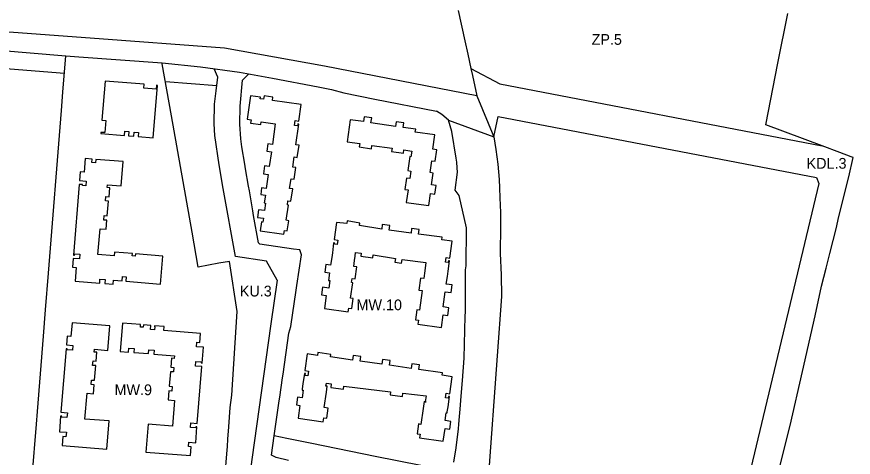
# Model space of a CAD drawing. Extents: x 7427060 to 7429122, y 5545301 to 5546237.
# Drawn here: x 7428222.9 to 7428612.5, y 5545719.4 to 5545924.5 of the extents above; entities that cross this region are included whole.
import ezdxf

# ---------------------------------------------------------------- set-up
doc = ezdxf.new("R2010")
doc.units = 0
for name, color, linetype in [('LIN_Linia Zabudowy Nieprzekraczalna', 7, 'Continuous'), ('LIN_Linia Zabudowy Obowiązujaca', 7, 'Continuous'), ('LIN_Linie Rozgraniczajace', 7, 'Continuous'), ('TXT_Oznaczenia Przeznaczenia', 7, 'Continuous')]:
    doc.layers.add(name, color=color, linetype=linetype)

msp = doc.modelspace()

# ---------------------------------------------------------------- linework, layer by layer
at = {"layer": 'LIN_Linia Zabudowy Nieprzekraczalna'}
msp.add_line((7428316.07, 5545892.32), (7428292.15, 5545894.23), dxfattribs=at)
msp.add_lwpolyline([(7428245.15, 5545897.99), (7428161.59, 5545904.67), (7428139.66, 5545906.42), (7428026.47, 5545915.47), (7427978.93, 5545906.35), (7427970.86, 5545904.87), (7427949.14, 5545903.31), (7427927.98, 5545847.56), (7427923.31, 5545834.83), (7427920.46, 5545827.63), (7427909.28, 5545797.22), (7427905.07, 5545749.44), (7427892.52, 5545606.57)], dxfattribs=at)
at = {"layer": 'LIN_Linia Zabudowy Obowiązujaca'}
for p, q in [((7428369.92, 5545814.52), (7428369.62, 5545812.41)), ((7428380.25, 5545810.91), (7428380.56, 5545813.02)), ((7428413.12, 5545807.42), (7428412.81, 5545805.06)), ((7428423.47, 5545803.55), (7428423.82, 5545806)), ((7428355.92, 5545751.26), (7428355.83, 5545750.67)), ((7428356.2, 5545753.64), (7428355.92, 5545751.26)), ((7428412.22, 5545742.13), (7428411.16, 5545734.71)), ((7428423.43, 5545740.53), (7428423.79, 5545742.92))]:
    msp.add_line(p, q, dxfattribs=at)
for points in [[(7428262.09, 5545870.16), (7428273.05, 5545869.25), (7428273.21, 5545871.19), (7428275.15, 5545871.03), (7428274.99, 5545869.09), (7428277.53, 5545868.89), (7428277.69, 5545870.68), (7428279.68, 5545870.5), (7428279.53, 5545868.71), (7428286.51, 5545868.14), (7428288.52, 5545892.51), (7428288.02, 5545892.56), (7428287.86, 5545890.77), (7428282.09, 5545891.23), (7428282.23, 5545893.02), (7428264.09, 5545894.47), (7428262.59, 5545876.36), (7428264.38, 5545876.21), (7428263.92, 5545870.5), (7428262.13, 5545870.64)], [(7428347.38, 5545823.2), (7428347.65, 5545824.96), (7428348.93, 5545824.77), (7428349.65, 5545829.51), (7428348.47, 5545829.69), (7428349.55, 5545836.81), (7428348.95, 5545836.9), (7428349.25, 5545838.83), (7428350.61, 5545838.62), (7428351.47, 5545844.31), (7428349.98, 5545844.53), (7428350.66, 5545848.98), (7428352.2, 5545848.77), (7428352.95, 5545854.25), (7428351.47, 5545854.47), (7428352.14, 5545859.17), (7428353.58, 5545858.96), (7428354.39, 5545864.65), (7428352.94, 5545864.86), (7428354.31, 5545874.46), (7428353.87, 5545874.53), (7428353.74, 5545873.64), (7428352.23, 5545873.85), (7428352.55, 5545876.13), (7428354.33, 5545875.87), (7428355.43, 5545883.6), (7428342.07, 5545885.5), (7428342.24, 5545887.03), (7428338.13, 5545887.61), (7428337.83, 5545886.11), (7428336.37, 5545886.31), (7428336.52, 5545887.03), (7428331.79, 5545887.71), (7428330.3, 5545876.79), (7428332.07, 5545876.49), (7428331.81, 5545874.99), (7428336.62, 5545874.36), (7428336.78, 5545875.55), (7428343.32, 5545874.68), (7428342.05, 5545865.06), (7428339.87, 5545865.37), (7428339.36, 5545861.81), (7428341.54, 5545861.5), (7428340.56, 5545854.67), (7428338.38, 5545854.98), (7428337.86, 5545851.33), (7428340.04, 5545851.02), (7428339.11, 5545844.54), (7428336.99, 5545844.84), (7428336.54, 5545841.72), (7428338.72, 5545841.4), (7428338.21, 5545837.84), (7428338.81, 5545837.75), (7428338.3, 5545834.19), (7428335.53, 5545834.59), (7428335.02, 5545831.02), (7428337.79, 5545830.63), (7428337.54, 5545828.85), (7428336.94, 5545828.93), (7428336.34, 5545824.73)], [(7428376.76, 5545866.26), (7428382.63, 5545865.41), (7428382.4, 5545863.84), (7428388.07, 5545863.03), (7428388.29, 5545864.59), (7428397.71, 5545863.24), (7428397.49, 5545861.76), (7428402.98, 5545860.97), (7428403.19, 5545862.44), (7428406.9, 5545861.91), (7428406.52, 5545859.27), (7428405.93, 5545859.35), (7428404.99, 5545852.83), (7428406.43, 5545852.62), (7428405.94, 5545849.16), (7428404.47, 5545849.37), (7428403.72, 5545844.11), (7428405.2, 5545843.9), (7428404.35, 5545838), (7428414.8, 5545836.51), (7428415.61, 5545842.2), (7428417.62, 5545841.92), (7428418.19, 5545845.88), (7428416.13, 5545846.18), (7428416.91, 5545851.67), (7428415.47, 5545851.88), (7428416.25, 5545857.36), (7428417.74, 5545857.15), (7428418.51, 5545862.5), (7428416.63, 5545862.77), (7428417.58, 5545869.43), (7428408.53, 5545870.72), (7428408.73, 5545872.08), (7428402.86, 5545872.91), (7428403.16, 5545875.03), (7428399.58, 5545875.54), (7428399.27, 5545873.44), (7428387.89, 5545875.06), (7428388.22, 5545877.36), (7428384.79, 5545877.85), (7428384.48, 5545875.65), (7428378.23, 5545876.54)], [(7428260.76, 5545813.74), (7428261.76, 5545825.8), (7428264.57, 5545825.57), (7428264.94, 5545829.69), (7428263.5, 5545829.82), (7428263.69, 5545831.92), (7428265.13, 5545831.79), (7428265.75, 5545838.56), (7428264.31, 5545838.69), (7428264.5, 5545840.79), (7428265.94, 5545840.66), (7428266.32, 5545844.84), (7428265.03, 5545844.96), (7428265.15, 5545846.21), (7428271.5, 5545845.72), (7428272.44, 5545857.02), (7428259.73, 5545858.05), (7428259.6, 5545856.46), (7428257.93, 5545856.59), (7428258.08, 5545858.18), (7428254.83, 5545858.47), (7428254.32, 5545852.15), (7428252.45, 5545852.3), (7428252.12, 5545848.23), (7428255.29, 5545847.97), (7428255.11, 5545845.76), (7428253.5, 5545845.89), (7428253.52, 5545846.29), (7428251.97, 5545846.42), (7428249.31, 5545813.52), (7428249.81, 5545813.49), (7428249.84, 5545814.06), (7428252.34, 5545813.92), (7428252.21, 5545811.71), (7428249.18, 5545811.91), (7428248.85, 5545807.82), (7428250.62, 5545807.67), (7428250.13, 5545801.38), (7428261.57, 5545800.49), (7428261.71, 5545802.25), (7428264.15, 5545802.06), (7428264.01, 5545800.3), (7428267.85, 5545800), (7428267.99, 5545801.79), (7428271.98, 5545801.47), (7428272.14, 5545803.46), (7428273.9, 5545803.32), (7428273.74, 5545801.33), (7428289.9, 5545799.97), (7428291.01, 5545813.06), (7428278.18, 5545814.12), (7428278.08, 5545813), (7428276.77, 5545813.12), (7428276.87, 5545814.24), (7428268.5, 5545814.92), (7428268.35, 5545813.11)], [(7428265.93, 5545736.27), (7428254.72, 5545737.16), (7428255.67, 5545749.18), (7428258.71, 5545748.94), (7428259.04, 5545753.13), (7428257.59, 5545753.24), (7428257.75, 5545755.35), (7428259.21, 5545755.23), (7428259.75, 5545762.04), (7428258.29, 5545762.15), (7428258.46, 5545764.25), (7428259.91, 5545764.13), (7428260.24, 5545768.28), (7428259, 5545768.38), (7428259.1, 5545769.64), (7428265.44, 5545769.12), (7428266.36, 5545780.49), (7428248.71, 5545781.92), (7428248.2, 5545775.64), (7428246.41, 5545775.79), (7428246.08, 5545771.7), (7428249.07, 5545771.46), (7428248.89, 5545769.26), (7428246.4, 5545769.47), (7428246.44, 5545769.89), (7428245.94, 5545769.93), (7428243.52, 5545740.3), (7428246.51, 5545740.06), (7428246.34, 5545737.87), (7428243.84, 5545738.07), (7428243.88, 5545738.49), (7428243.38, 5545738.53), (7428242.8, 5545731.29), (7428246.06, 5545731.03), (7428245.88, 5545728.94), (7428244.43, 5545729.06), (7428244.08, 5545724.87), (7428264.86, 5545723.16)], [(7428272.25, 5545781.79), (7428271.18, 5545768.68), (7428275, 5545768.37), (7428275.14, 5545770.17), (7428277.61, 5545769.97), (7428277.46, 5545768.17), (7428284.28, 5545767.62), (7428284.42, 5545769.42), (7428286.88, 5545769.22), (7428286.74, 5545767.42), (7428296.38, 5545766.64), (7428296.29, 5545765.38), (7428295, 5545765.49), (7428294.65, 5545761.31), (7428296.11, 5545761.18), (7428295.93, 5545759.09), (7428294.48, 5545759.21), (7428293.92, 5545752.43), (7428295.37, 5545752.31), (7428295.2, 5545750.21), (7428293.74, 5545750.33), (7428293.4, 5545746.12), (7428296.43, 5545745.87), (7428295.43, 5545733.83), (7428284.21, 5545734.78), (7428283.1, 5545721.79), (7428303.87, 5545720.15), (7428304.19, 5545724.23), (7428302.87, 5545724.33), (7428303.04, 5545726.42), (7428306.28, 5545726.16), (7428306.85, 5545733.54), (7428306.35, 5545733.58), (7428306.31, 5545733.01), (7428303.82, 5545733.22), (7428304, 5545735.41), (7428306.99, 5545735.16), (7428309.15, 5545761.62), (7428306.17, 5545761.85), (7428306.34, 5545764.04), (7428308.81, 5545763.84), (7428308.77, 5545763.27), (7428309.27, 5545763.23), (7428309.86, 5545770.61), (7428306.64, 5545770.86), (7428306.8, 5545772.95), (7428308.23, 5545772.84), (7428308.56, 5545777.04), (7428291.45, 5545778.44), (7428291.59, 5545780.23), (7428287.08, 5545780.6), (7428287.04, 5545780.08), (7428287.19, 5545780.07), (7428287.08, 5545778.69), (7428285.16, 5545778.84), (7428285.32, 5545780.74), (7428281.91, 5545781.01), (7428281.82, 5545779.89), (7428280.52, 5545779.99), (7428280.61, 5545781.12)]]:
    msp.add_lwpolyline(points, close=True, dxfattribs=at)
for points in [[(7428423.82, 5545806), (7428424.46, 5545810.82), (7428424.02, 5545810.88), (7428423.9, 5545809.99), (7428422.56, 5545810.17), (7428422.85, 5545812.35), (7428424.64, 5545812.11), (7428425.69, 5545819.97), (7428420.93, 5545820.61), (7428421.09, 5545821.8), (7428410.09, 5545823.28), (7428410.39, 5545825.46), (7428406.82, 5545825.94), (7428406.53, 5545823.76), (7428396.42, 5545825.11), (7428396.71, 5545827.29), (7428393.17, 5545827.77), (7428392.88, 5545825.59), (7428382.58, 5545827.25), (7428382.78, 5545828.43), (7428376.85, 5545829.39), (7428376.66, 5545828.21), (7428371.89, 5545828.72), (7428370.81, 5545820.7), (7428372.4, 5545820.51), (7428372.15, 5545818.43), (7428370.95, 5545818.57), (7428371.02, 5545819.12), (7428370.47, 5545819.19), (7428369.92, 5545814.52)], [(7428380.56, 5545813.02), (7428380.76, 5545814.66), (7428383.29, 5545814.36), (7428383.18, 5545813.02), (7428388.72, 5545812.2), (7428388.96, 5545813.56), (7428399.24, 5545811.97)], [(7428369.62, 5545812.41), (7428369.11, 5545808.85), (7428366.94, 5545809.16), (7428366.43, 5545805.59), (7428368.61, 5545805.28), (7428368.11, 5545801.72), (7428368.7, 5545801.64), (7428368.21, 5545798.12), (7428365.39, 5545798.52), (7428364.88, 5545794.93), (7428367.05, 5545794.62), (7428366.21, 5545788.65), (7428377.29, 5545787.09), (7428377.52, 5545788.77), (7428378.91, 5545788.57), (7428379.58, 5545793.31), (7428378.39, 5545793.47), (7428379.4, 5545800.6), (7428378.8, 5545800.69), (7428379.08, 5545802.62), (7428380.51, 5545802.41), (7428381.3, 5545807.99), (7428379.86, 5545808.19), (7428380.25, 5545810.91)], [(7428399.24, 5545811.97), (7428398.96, 5545810.2), (7428402.15, 5545809.71), (7428402.43, 5545811.52), (7428413.47, 5545810.05), (7428413.12, 5545807.42)], [(7428412.81, 5545805.06), (7428412.46, 5545802.58), (7428411.02, 5545802.79), (7428410.23, 5545797.19), (7428411.72, 5545796.98), (7428410.44, 5545787.92), (7428409.3, 5545788.08), (7428408.63, 5545783.33), (7428410.01, 5545783.13), (7428409.76, 5545781.31), (7428420.69, 5545779.76), (7428421.52, 5545785.7), (7428423.7, 5545785.4), (7428424.21, 5545788.96), (7428421.48, 5545789.35), (7428422.49, 5545796.44), (7428425.26, 5545796.05), (7428425.77, 5545799.65), (7428422.97, 5545800.04), (7428423.47, 5545803.55)], [(7428423.79, 5545742.92), (7428424.46, 5545747.67), (7428424.01, 5545747.73), (7428423.89, 5545746.84), (7428422.55, 5545747.03), (7428422.86, 5545749.21), (7428424.64, 5545748.96), (7428425.76, 5545756.86), (7428421, 5545757.53), (7428421.17, 5545758.72), (7428410.23, 5545760.27), (7428410.54, 5545762.45), (7428406.95, 5545762.95), (7428406.65, 5545760.77), (7428396.57, 5545762.2), (7428396.87, 5545764.38), (7428393.31, 5545764.88), (7428393, 5545762.7), (7428382.88, 5545764.13), (7428383.19, 5545766.31), (7428379.63, 5545766.82), (7428379.32, 5545764.64), (7428369, 5545766.1), (7428369.16, 5545767.23), (7428363.18, 5545768.08), (7428362.99, 5545766.69), (7428358.22, 5545767.6), (7428357.07, 5545759.76), (7428358.83, 5545759.51), (7428358.51, 5545757.31), (7428357.22, 5545757.5), (7428357.35, 5545758.39), (7428356.91, 5545758.45), (7428356.2, 5545753.64)], [(7428366.91, 5545752.5), (7428367.13, 5545753.93), (7428369.36, 5545753.6), (7428369.14, 5545751.81), (7428375.13, 5545751.08), (7428375.31, 5545752.55), (7428397.05, 5545749.91), (7428396.87, 5545748.42), (7428402.52, 5545747.73), (7428402.7, 5545749.22), (7428413.52, 5545747.91), (7428413.2, 5545745.2), (7428413.64, 5545745.14)], [(7428367.15, 5545749.67), (7428367.53, 5545752.41), (7428366.91, 5545752.5)], [(7428355.83, 5545750.67), (7428356.38, 5545750.59), (7428355.87, 5545747.03), (7428353.69, 5545747.33), (7428353.19, 5545743.77), (7428354.7, 5545743.53), (7428354, 5545737.63), (7428365.62, 5545735.95), (7428365.87, 5545737.74), (7428367.26, 5545737.54), (7428367.93, 5545742.29), (7428366.14, 5545742.55), (7428367.15, 5545749.67)], [(7428413.64, 5545745.14), (7428412.6, 5545745.27), (7428412.22, 5545742.13)], [(7428411.16, 5545734.71), (7428410.01, 5545734.88), (7428409.4, 5545730.26), (7428410.79, 5545730.06), (7428410.5, 5545728.46), (7428421.55, 5545726.88), (7428422.4, 5545732.84), (7428424.58, 5545732.53), (7428425.09, 5545736.09), (7428422.37, 5545736.48), (7428422.88, 5545740.1), (7428423.36, 5545740.03), (7428423.43, 5545740.53)]]:
    msp.add_lwpolyline(points, dxfattribs=at)
at = {"layer": 'LIN_Linie Rozgraniczajace'}
for p, q in [((7428424.03, 5545876.28), (7428445.04, 5545868.63)), ((7428448.17, 5545833.31), (7428448.26, 5545826.9)), ((7428232.09, 5545734.84), (7428232.56, 5545740.74)), ((7428228.22, 5545686.48), (7428232.09, 5545734.84)), ((7428341.5, 5545720.4), (7428342.76, 5545729.33))]:
    msp.add_line(p, q, dxfattribs=at)
for points in [[(7428428.5, 5545927.32), (7428431.59, 5545913.27), (7428432.96, 5545907.07), (7428434.43, 5545900.42), (7428434.45, 5545900.33), (7428435.16, 5545897.11), (7428437.23, 5545887.71), (7428366.32, 5545901.4), (7428319.62, 5545909.88), (7428257.14, 5545914.47), (7428149.82, 5545922.39), (7428036.1, 5545930.31)], [(7428576.58, 5545708.32), (7428583.05, 5545734.15), (7428588.76, 5545759.36), (7428594.77, 5545785.19), (7428597.67, 5545799.03), (7428599.82, 5545807.37), (7428600.96, 5545811.82), (7428601.57, 5545814.19), (7428604.68, 5545826.28), (7428605.52, 5545830.9), (7428610.35, 5545849.98), (7428612.46, 5545858.88), (7428611.48, 5545859.24), (7428606.23, 5545861.22), (7428597.94, 5545864.34), (7428571.7, 5545874.21), (7428577.41, 5545902.88), (7428581.99, 5545925.9)], [(7428168.15, 5545912.74), (7428245.82, 5545906.26), (7428251.8, 5545905.84), (7428290.66, 5545903.06), (7428308.47, 5545901.13), (7428326.64, 5545898.66), (7428341.98, 5545895.9), (7428363.37, 5545891.81), (7428369.47, 5545890.65), (7428375.19, 5545888.98), (7428389.67, 5545886.15), (7428418.37, 5545880.52)], [(7428243.77, 5545880.74), (7428244.46, 5545889.37), (7428245.82, 5545906.26)], [(7428311.93, 5545631.84), (7428316.77, 5545665.44), (7428320.07, 5545711.32), (7428320.77, 5545721.01), (7428321.02, 5545724.45), (7428321.26, 5545727.8), (7428321.68, 5545733.6), (7428322.32, 5545742.57), (7428323.1, 5545748.28), (7428325.54, 5545787.29), (7428322.05, 5545810.56), (7428317.04, 5545809.67), (7428307.43, 5545807.94), (7428304.57, 5545824.21), (7428295.03, 5545878.33), (7428290.65, 5545902.51), (7428290.66, 5545903.06)], [(7428344.16, 5545801.75), (7428339.2, 5545810.69), (7428324.84, 5545812.85), (7428319.11, 5545844.49), (7428317.21, 5545855.55), (7428315.22, 5545869.12), (7428314.94, 5545874.54), (7428315.08, 5545883.7), (7428315.77, 5545890.02), (7428316.58, 5545896.3), (7428314.83, 5545900.26)], [(7428434.45, 5545900.33), (7428447.89, 5545893.21), (7428597.95, 5545864.33)], [(7428342.76, 5545729.33), (7428345.14, 5545745.68), (7428345.38, 5545747.38), (7428346.69, 5545756.43), (7428346.93, 5545758.06), (7428349.58, 5545777.18), (7428350.61, 5545780.2), (7428353.09, 5545797.17), (7428353.35, 5545799.28), (7428355.49, 5545813.6), (7428354.71, 5545815.89), (7428351.74, 5545816.32), (7428336.12, 5545818.54), (7428335.55, 5545819.14), (7428333.26, 5545831.87), (7428332.95, 5545834.07), (7428331.36, 5545843.35), (7428330.94, 5545845.59), (7428329.49, 5545853.59), (7428329.11, 5545855.79), (7428327.77, 5545863.9), (7428327.27, 5545867.64), (7428326.79, 5545874.47), (7428326.93, 5545882.84), (7428328.13, 5545895.01), (7428331.06, 5545897.86)], [(7428437.23, 5545887.71), (7428445.05, 5545868.61), (7428446.09, 5545862.61), (7428446.89, 5545855.84), (7428447.26, 5545852.26), (7428447.52, 5545848.66), (7428447.72, 5545844.77), (7428447.91, 5545840.19), (7428448.17, 5545833.31)], [(7428236.35, 5545788.04), (7428237.71, 5545805.09), (7428243.77, 5545880.74)], [(7428426.52, 5545717.08), (7428427.52, 5545723.79), (7428428.62, 5545732.69), (7428428.87, 5545734.78), (7428429.58, 5545743.7), (7428429.74, 5545745.89), (7428430.49, 5545755.05), (7428431.35, 5545765.51), (7428431.82, 5545784.99), (7428431.86, 5545787.04), (7428431.97, 5545795.84), (7428431.9, 5545798.03), (7428431.97, 5545806.62), (7428432.15, 5545808.57), (7428432.38, 5545826.17), (7428428.94, 5545841.31), (7428427.13, 5545843.75), (7428428.11, 5545852.1), (7428428.04, 5545854.07), (7428427.85, 5545856.81), (7428427.59, 5545858.59), (7428425.59, 5545871.01), (7428424.03, 5545876.28), (7428420.88, 5545878.99), (7428418.37, 5545880.52)], [(7428445.05, 5545868.61), (7428447.12, 5545878.09), (7428595.29, 5545849.57), (7428596.44, 5545846.87), (7428538.12, 5545602.56), (7428537.53, 5545599.5), (7428537.18, 5545594.94), (7428537.63, 5545583.4)], [(7428448.26, 5545826.9), (7428448.08, 5545814.22), (7428448.49, 5545804.28), (7428448.69, 5545794.28), (7428446.65, 5545766.53), (7428442.42, 5545709.16), (7428442.05, 5545704.04), (7428441.48, 5545695.08)], [(7428344.16, 5545801.75), (7428341.32, 5545781.52), (7428333.55, 5545726.1), (7428332.61, 5545719.37), (7428324.93, 5545664.31), (7428324.51, 5545661.28), (7428323.83, 5545656.49), (7428320.04, 5545629.35), (7428319.1, 5545622.6), (7428317.9, 5545614.05), (7428316.54, 5545604.3), (7428311.51, 5545568.77), (7428309.63, 5545555.44), (7428309.1, 5545551.64)], [(7428232.56, 5545740.74), (7428235.36, 5545775.71), (7428236.35, 5545788.04)], [(7428426.05, 5545712.47), (7428425.07, 5545712.67), (7428416.79, 5545714.34), (7428411.16, 5545715.48), (7428389.87, 5545719.79), (7428360.39, 5545725.76), (7428348.77, 5545728.11), (7428342.76, 5545729.33)], [(7428349.47, 5545717.95), (7428343.73, 5545719.2), (7428341.5, 5545720.4)]]:
    msp.add_lwpolyline(points, dxfattribs=at)

# ---------------------------------------------------------------- texts
at = {"layer": 'TXT_Oznaczenia Przeznaczenia'}
for s, p in [('ZP.5', (7428490.62, 5545911.39)), ('KU.3', (7428326.82, 5545794.24))]:
    msp.add_text(s, height=5, dxfattribs=at).set_placement(p)
for s, p in [('KDL.3', (7428590.73, 5545853.71)), ('MW.10', (7428381.14, 5545787.84)), ('MW.9', (7428268.48, 5545748.3))]:
    msp.add_text(s, height=5, rotation=360, dxfattribs=at).set_placement(p)

doc.saveas('drawing.dxf')
